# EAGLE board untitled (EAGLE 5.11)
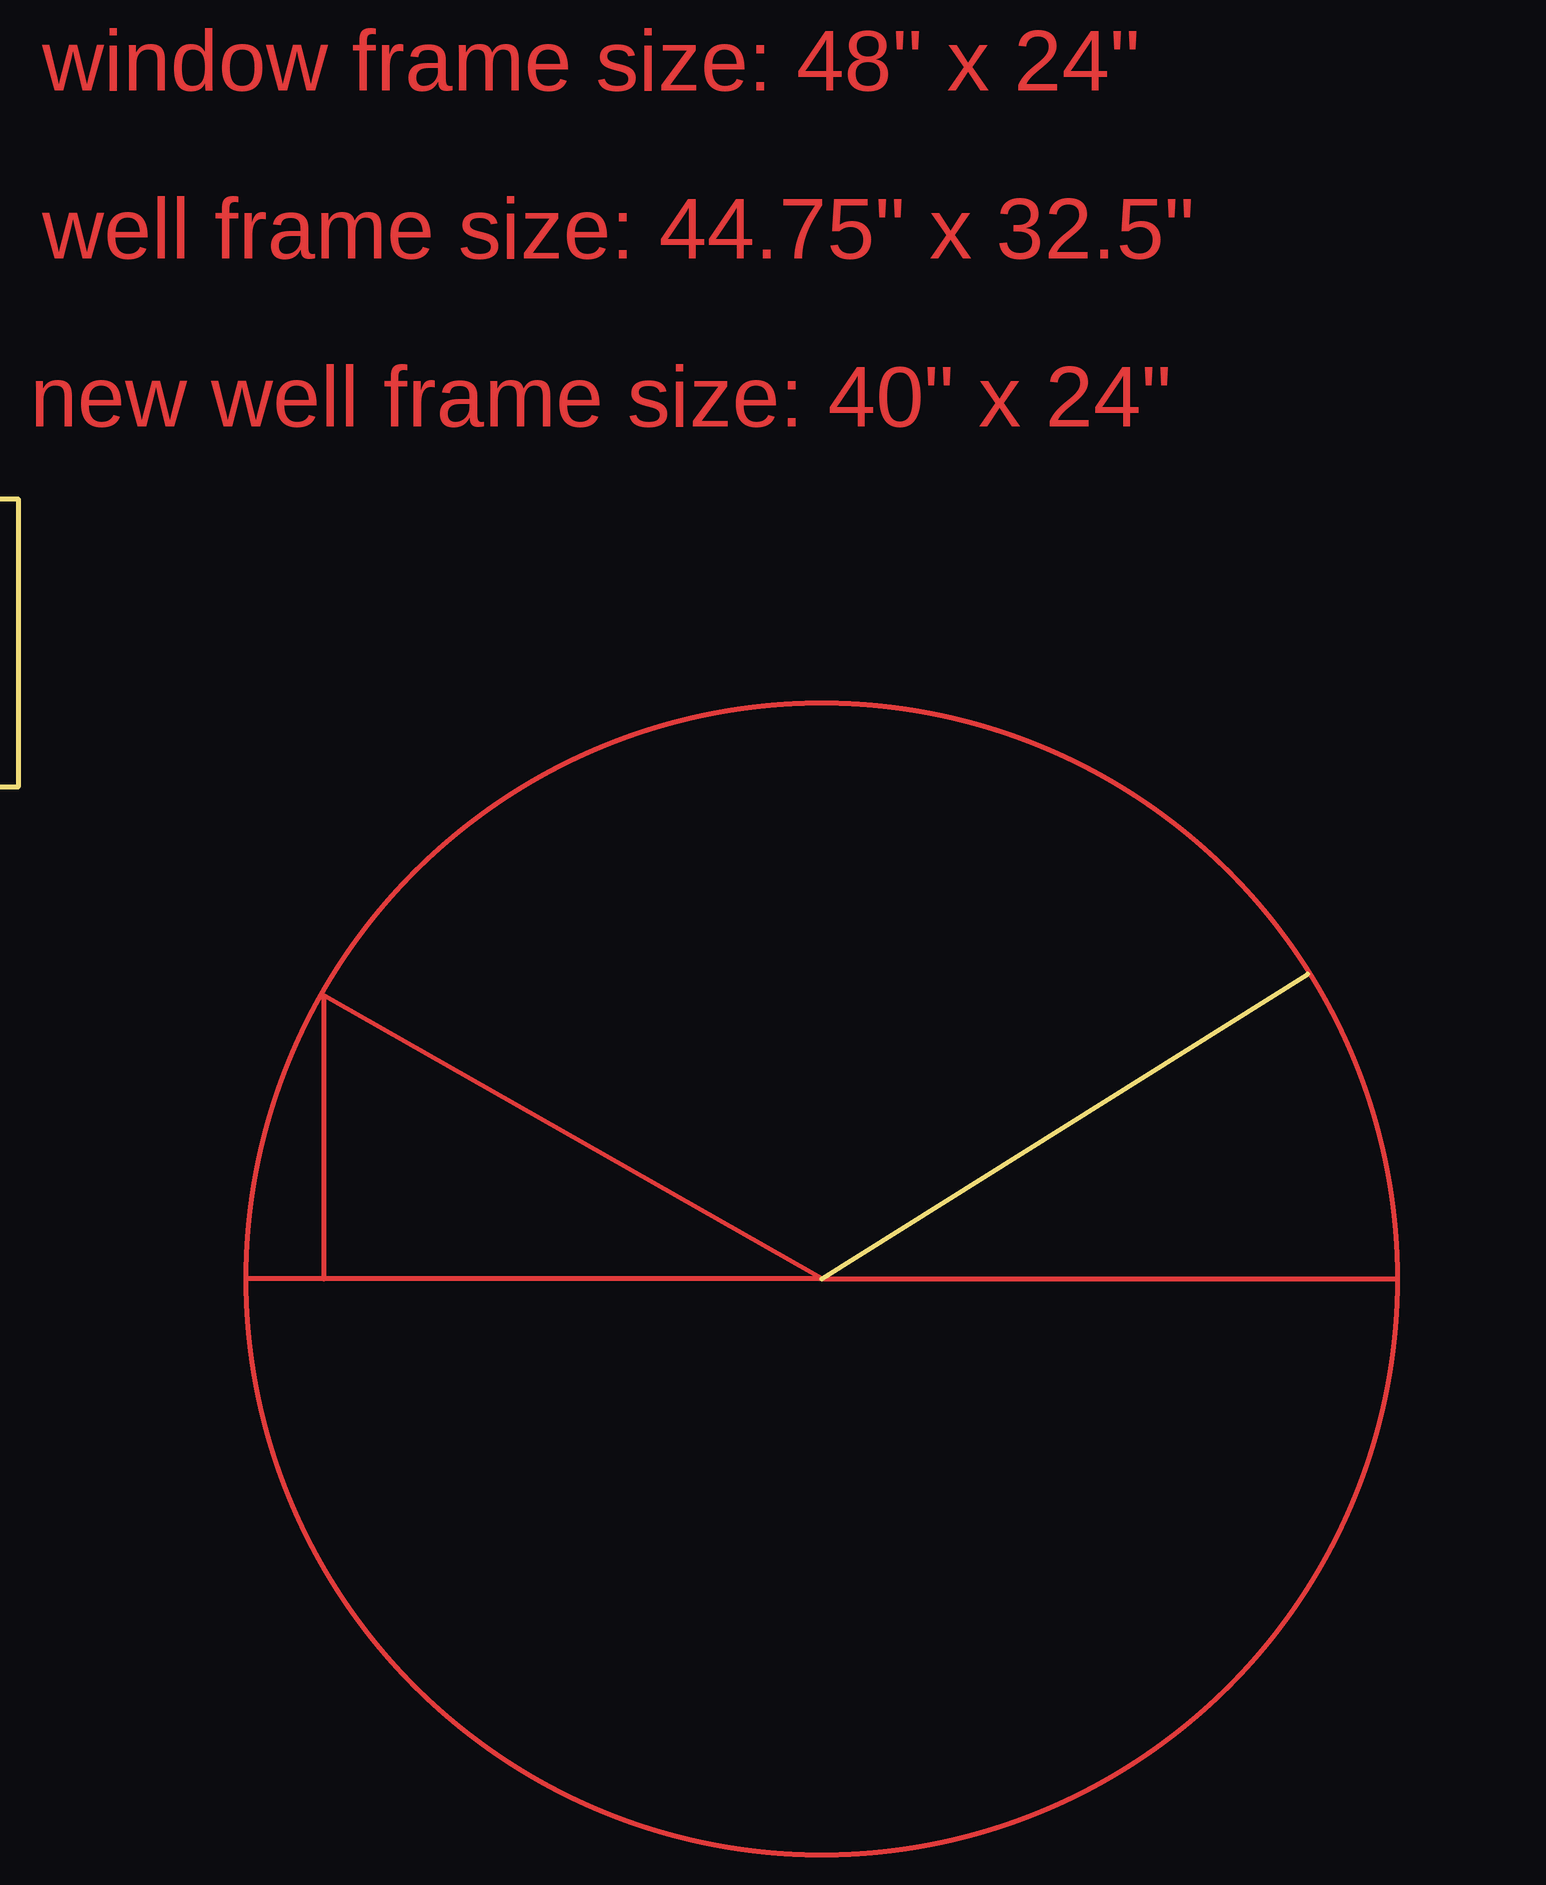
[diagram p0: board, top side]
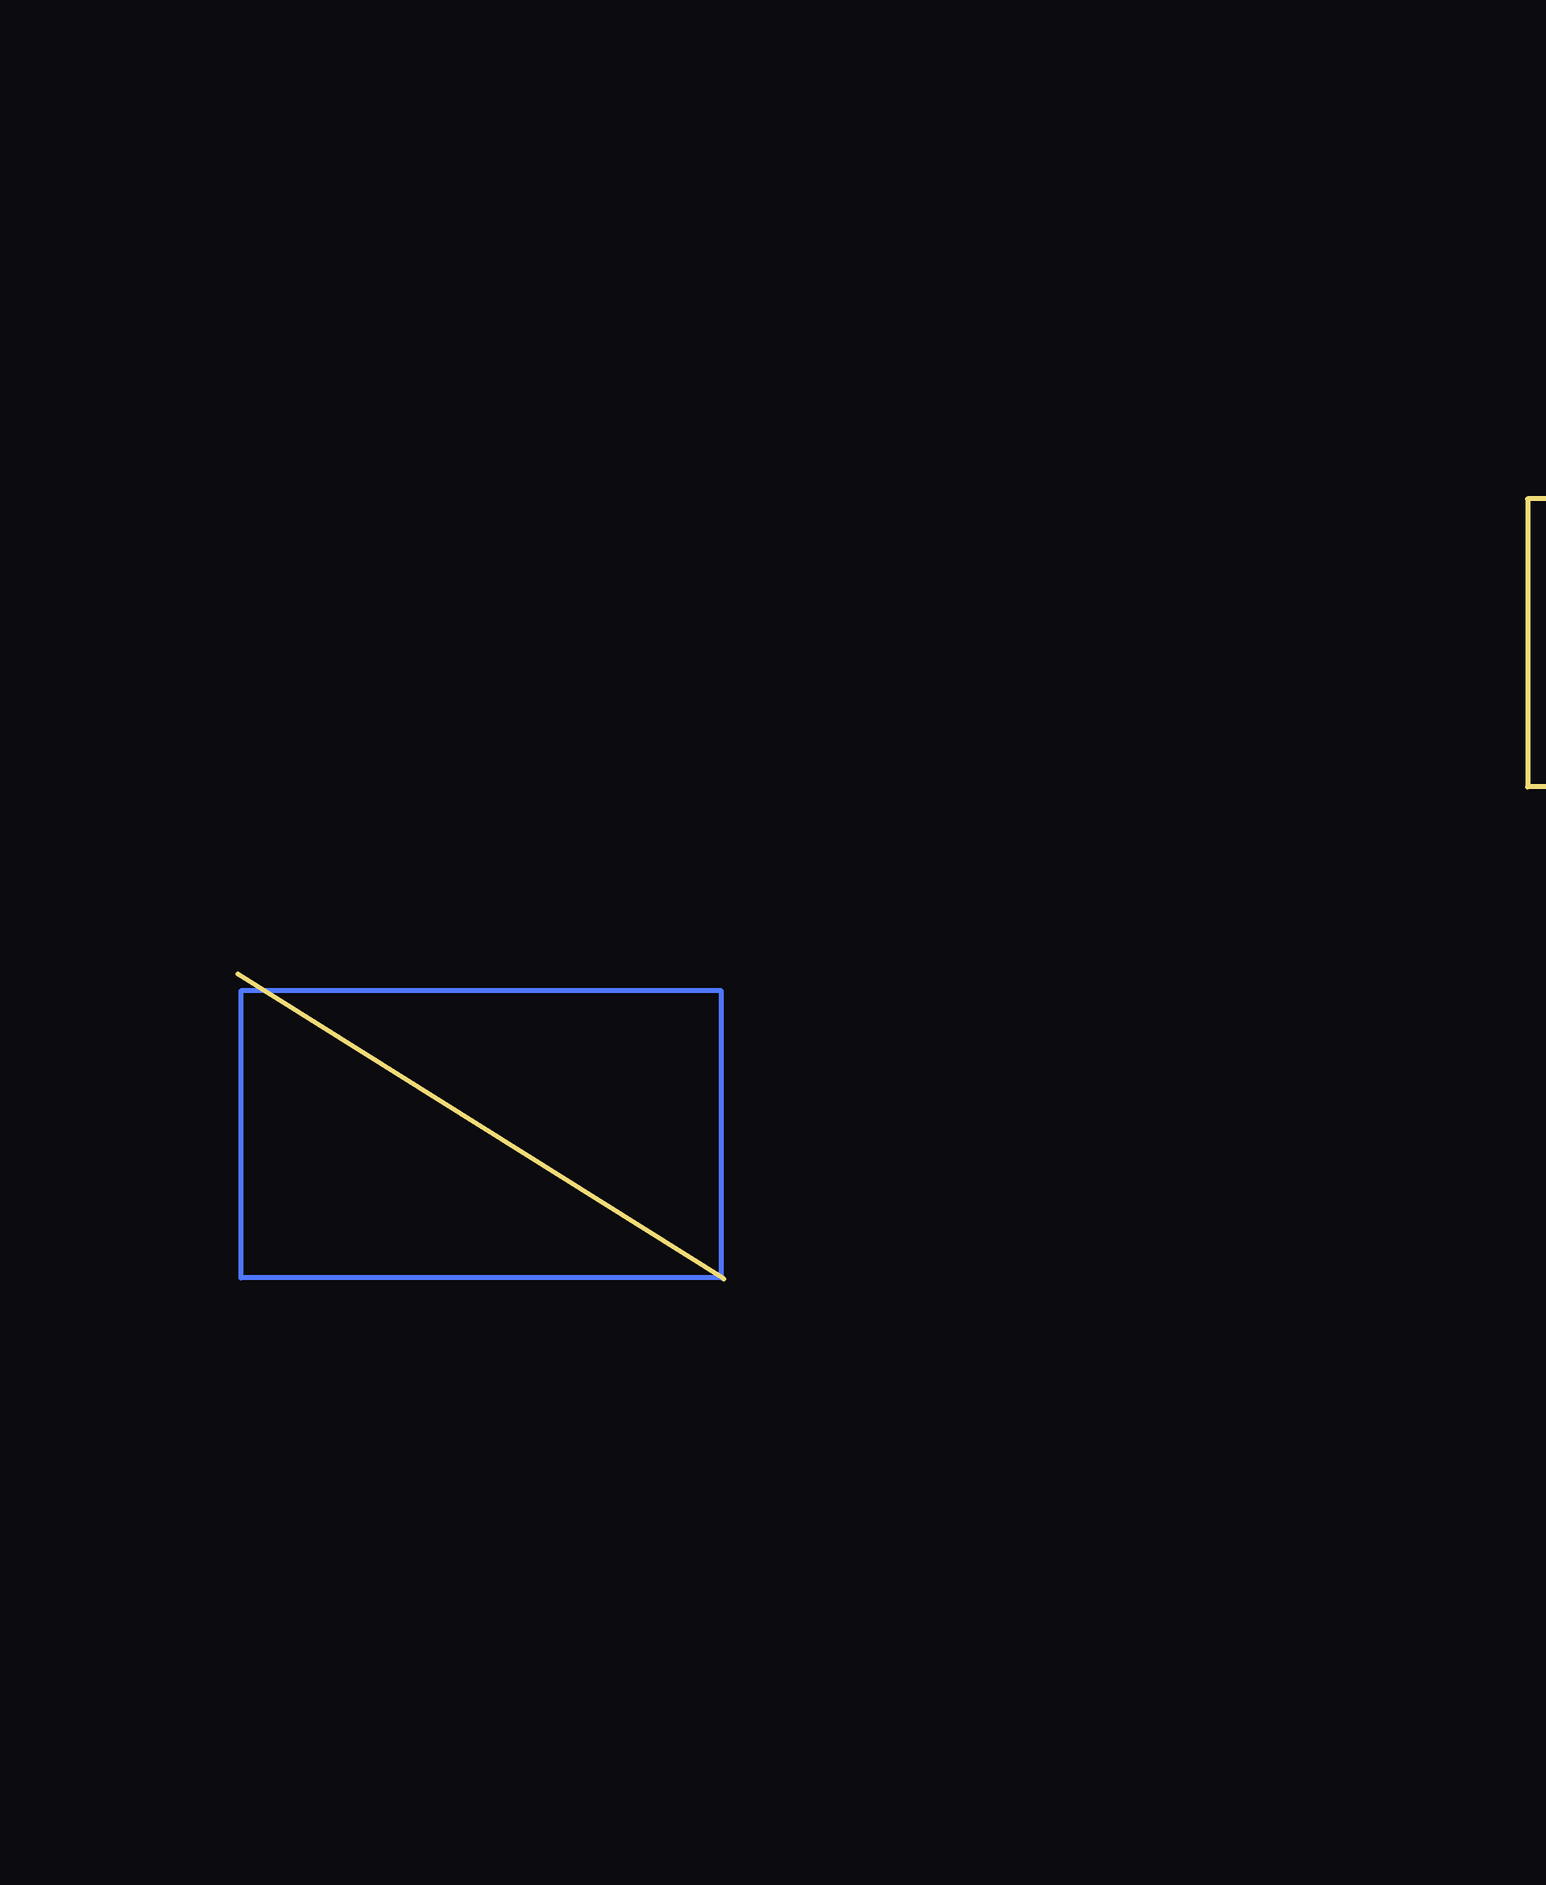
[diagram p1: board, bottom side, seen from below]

No outline drawn. Coordinates in mm, seen from the top.
Copper layers (1*16): Top 0.035mm / dielectric 1.5mm / Bottom 0.035mm
Design rules "default": minimum track width 10mil, minimum drill 24mil, track to track 8mil, track to pad 8mil, pad to pad 8mil, via to via 8mil, smd to smd 8mil, copper to edge 40mil, drill to drill 8mil, minimum pad ring 10mil, minimum via ring 8mil, stop-mask expansion 4mil, vias tented up to drill 0mil, thermal gap 10mil
Milling: 5 lines

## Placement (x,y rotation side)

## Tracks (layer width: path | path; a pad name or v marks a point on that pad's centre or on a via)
N$1
  Top 0.406: -41.5,0 -48,0 | 0,0 -41.5,0 | 0,0 48,0 | 0,0 -41.5,23.6 -41.5,0
N$3
  Bottom 0.406: 0.2,0.1 40.25,0.1 40.25,24 0.2,24 0.2,0.1
(copper drawn outside any net)
  shapes: Top circle x1

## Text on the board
Top: window frame size: 48" x 24" | well frame size: 44.75" x 32.5" | new well frame size: 40" x 24"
